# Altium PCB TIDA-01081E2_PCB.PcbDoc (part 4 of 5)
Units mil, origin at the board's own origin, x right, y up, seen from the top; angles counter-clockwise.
Board outline 8611.33 x 3169.64 mil, 4 copper layers (Top Layer, VCC, GND, Bottom Layer), stack 61.6 mil thick; 411 components, 187 nets, 1087 pads, 1987 vias.
Unrouted connection lines stored in the file: 7.
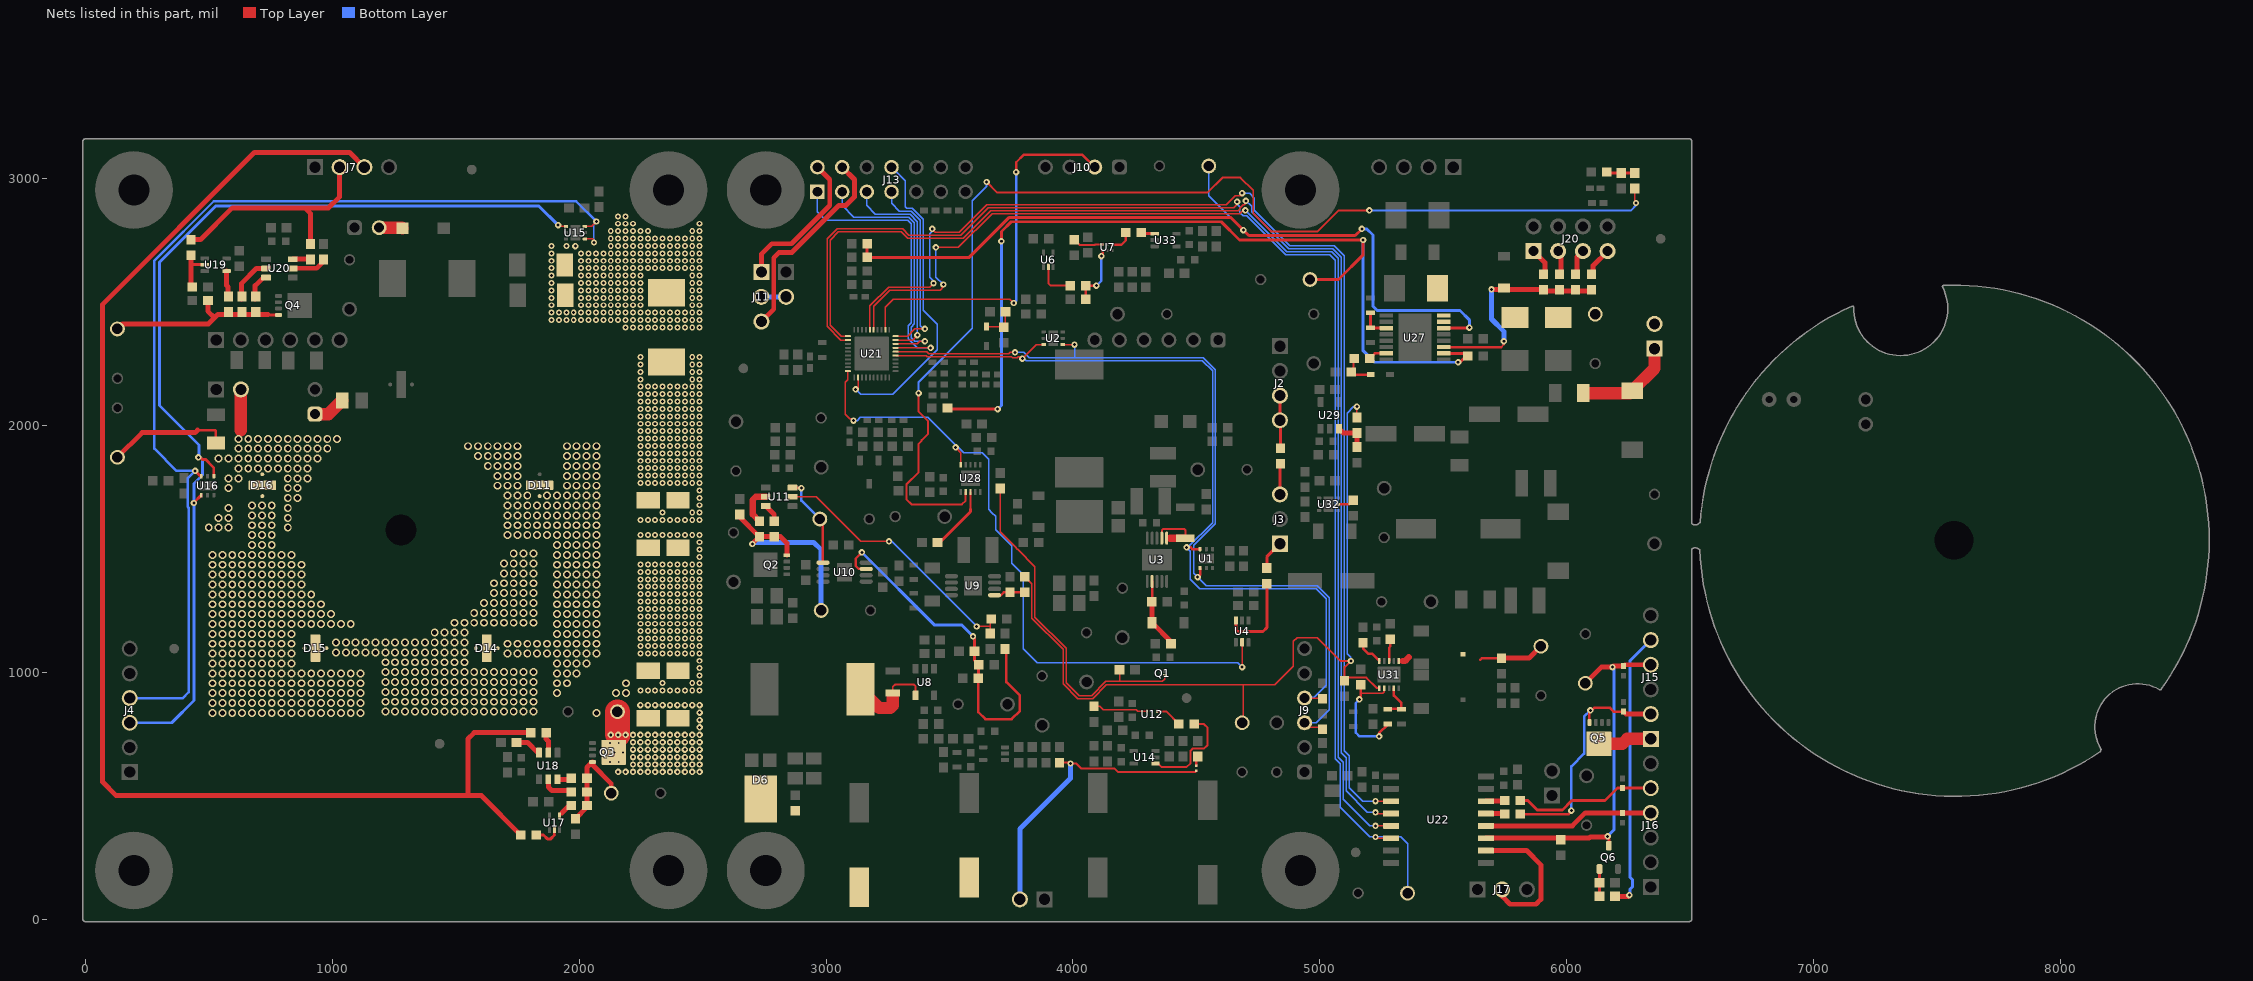
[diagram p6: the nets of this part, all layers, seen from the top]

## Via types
v1: diameter 32, hole 20, Top Layer to Bottom Layer, tented both sides, 779 vias
v2: diameter 26, hole 12, Top Layer to Bottom Layer, tented both sides, 622 vias
v3: diameter 24, hole 12, Top Layer to Bottom Layer, 506 vias
v4: diameter 19.68, hole 7.87, Top Layer to Bottom Layer, 50 vias
v5: diameter 26, hole 12, Top Layer to Bottom Layer, 14 vias
v6: diameter 19.68, hole 7.87, Top Layer to Bottom Layer, tented both sides, 12 vias
v7: diameter 19.68, hole 7.87, Top Layer to Bottom Layer, tented top, 4 vias

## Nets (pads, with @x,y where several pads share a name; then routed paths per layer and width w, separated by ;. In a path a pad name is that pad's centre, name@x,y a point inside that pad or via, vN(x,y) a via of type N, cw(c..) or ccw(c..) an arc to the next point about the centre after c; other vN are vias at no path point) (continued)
NetD10_1: D10.1 R133.2 R134.2
  other v3: 2248,1616 2278,1616 2308,1616 2338,1616 2368,1616 2398,1616 2428,1616 2458,1616 2488,1616 2338,1646 2458,1646 2488,1646 2488,1676 2488,1706 2488,1736 2248,1766 2278,1766 2308,1766 2338,1766 2368,1766 2398,1766 2428,1766 2458,1766 2488,1766 2248,1796 2278,1796 2308,1796 2338,1796 2368,1796 2398,1796 2428,1796 2458,1796 2488,1796 2248,1826 2278,1826 2308,1826 2338,1826 2368,1826 2398,1826 2428,1826 2458,1826 2488,1826 2248,1856 2278,1856 2308,1856 2338,1856 2368,1856 2398,1856 2428,1856 2458,1856 2488,1856 2248,1886 2278,1886 2308,1886 2338,1886 2368,1886 2398,1886 2428,1886 2458,1886 2488,1886 2248,1916 2278,1916 2308,1916 2338,1916 2368,1916 2398,1916 2428,1916 2458,1916 2488,1916 2248,1946 2278,1946 2308,1946 2338,1946 2368,1946 2398,1946 2428,1946 2458,1946 2488,1946 2248,1976 2278,1976 2308,1976 2338,1976 2368,1976 2398,1976 2428,1976 2458,1976 2488,1976 2248,2006 2278,2006 2308,2006 2338,2006 2368,2006 2398,2006 2428,2006 2458,2006 2488,2006 2248,2036 2278,2036 2308,2036 2338,2036 2368,2036 2398,2036 2428,2036 2458,2036 2488,2036 2248,2066 2278,2066 2308,2066 2338,2066 2368,2066 2398,2066 2428,2066 2458,2066 2488,2066 2248,2096 2278,2096 2308,2096 2338,2096 2368,2096 2398,2096 2428,2096 2458,2096 2488,2096 2248,2126 2278,2126 2308,2126 2338,2126 2368,2126 2398,2126 2428,2126 2458,2126 2488,2126 2248,2156 2278,2156 2308,2156 2338,2156 2368,2156 2398,2156 2428,2156 2458,2156 2488,2156 2248,2186 2458,2186 2488,2186 2248,2216 2458,2216 2488,2216 2248,2246 2458,2246 2488,2246 2248,2276 2458,2276 2488,2276
NetD10_2: D10.2 R131.1 R132.1
  other v2: 1985,2725
  other v3: 2188,2396 2218,2396 2248,2396 2278,2396 2308,2396 2338,2396 2368,2396 2398,2396 2428,2396 2458,2396 2488,2396 1888,2426 1918,2426 1948,2426 1978,2426 2008,2426 2038,2426 2068,2426 2098,2426 2128,2426 2158,2426 2188,2426 2218,2426 2248,2426 2278,2426 2308,2426 2338,2426 2368,2426 2398,2426 2428,2426 2458,2426 2488,2426 1888,2456 1918,2456 1948,2456 1978,2456 2008,2456 2038,2456 2068,2456 2098,2456 2128,2456 2158,2456 2188,2456 2218,2456 2248,2456 2278,2456 2308,2456 2338,2456 2368,2456 2398,2456 2428,2456 2458,2456 2488,2456 1888,2486 2008,2486 2038,2486 2068,2486 2098,2486 2128,2486 2158,2486 2188,2486 2218,2486 2248,2486 2458,2486 2488,2486 1888,2516 2008,2516 2038,2516 2068,2516 2098,2516 2128,2516 2158,2516 2188,2516 2218,2516 2248,2516 2458,2516 2488,2516 1888,2546 2008,2546 2038,2546 2068,2546 2098,2546 2128,2546 2158,2546 2188,2546 2218,2546 2248,2546 2458,2546 2488,2546 1888,2576 2008,2576 2038,2576 2068,2576 2098,2576 2128,2576 2158,2576 2188,2576 2218,2576 2248,2576 2458,2576 2488,2576 1888,2606 2008,2606 2038,2606 2068,2606 2098,2606 2128,2606 2158,2606 2188,2606 2218,2606 2248,2606 2458,2606 2488,2606 1888,2636 2008,2636 2038,2636 2068,2636 2098,2636 2128,2636 2158,2636 2188,2636 2218,2636 2248,2636 2278,2636 2308,2636 2338,2636 2368,2636 2398,2636 2428,2636 2458,2636 2488,2636 1888,2666 2008,2666 2038,2666 2068,2666 2098,2666 2128,2666 2158,2666 2188,2666 2218,2666 2248,2666 2278,2666 2308,2666 2338,2666 2368,2666 2398,2666 2428,2666 2458,2666 2488,2666 1888,2696 2008,2696 2038,2696 2068,2696 2098,2696 2128,2696 2158,2696 2188,2696 2218,2696 2248,2696 2278,2696 2308,2696 2338,2696 2368,2696 2398,2696 2428,2696 2458,2696 2488,2696 1888,2726 1948,2726 2128,2726 2158,2726 2188,2726 2218,2726 2248,2726 2278,2726 2308,2726 2338,2726 2368,2726 2398,2726 2428,2726 2458,2726 2488,2726 2128,2756 2158,2756 2188,2756 2218,2756 2248,2756 2278,2756 2308,2756 2338,2756 2368,2756 2398,2756 2428,2756 2458,2756 2488,2756 2128,2786 2158,2786 2188,2786 2218,2786 2248,2786 2278,2786 2458,2786 2488,2786 2158,2816 2188,2816 2218,2816 2488,2816 2158,2846 2188,2846
NetD11_2: D11.2 D11.3 D14.1
  other v1: 2070,835 1910,915 2150,915 2190,915 1910,955 1950,955 2190,955 1910,995 1950,995 1990,995 1910,1035 1950,1035 1990,1035 2030,1035 1710,1075 1750,1075 1790,1075 1830,1075 1870,1075 1910,1075 1950,1075 1990,1075 2030,1075 2070,1075 1710,1115 1750,1115 1790,1115 1830,1115 1870,1115 1910,1115 1950,1115 1990,1115 2030,1115 2070,1115 1910,1155 1950,1155 1990,1155 2030,1155 2070,1155 1910,1195 1950,1195 1990,1195 2030,1195 2070,1195 1910,1235 1950,1235 1990,1235 2030,1235 2070,1235 1910,1275 1950,1275 1990,1275 2030,1275 2070,1275 1910,1315 1950,1315 1990,1315 2030,1315 2070,1315 1910,1355 1950,1355 1990,1355 2030,1355 2070,1355 1910,1395 1950,1395 1990,1395 2030,1395 2070,1395 1910,1435 1950,1435 1990,1435 2030,1435 2070,1435 1910,1475 1950,1475 1990,1475 2030,1475 2070,1475 1910,1515 1950,1515 1990,1515 2030,1515 2070,1515 1710,1555 1750,1555 1790,1555 1830,1555 1870,1555 1910,1555 1950,1555 1990,1555 2030,1555 2070,1555 1710,1595 1750,1595 1790,1595 1830,1595 1870,1595 1910,1595 1950,1595 1990,1595 2030,1595 2070,1595 1710,1635 1750,1635 1790,1635 1830,1635 1870,1635 1910,1635 1950,1635 1990,1635 2030,1635 2070,1635 1710,1675 1750,1675 1790,1675 1830,1675 1870,1675 1910,1675 1950,1675 1990,1675 2030,1675 2070,1675 1710,1715 1750,1715 1790,1715 1870,1715 1910,1715 1950,1715 1990,1715 2030,1715 2070,1715 1670,1755 1710,1755 1750,1755 1950,1755 1990,1755 2030,1755 2070,1755 1670,1795 1710,1795 1750,1795 1950,1795 1990,1795 2030,1795 2070,1795 1630,1835 1670,1835 1710,1835 1750,1835 1950,1835 1990,1835 2030,1835 2070,1835 1590,1875 1630,1875 1670,1875 1710,1875 1750,1875 1950,1875 1990,1875 2030,1875 2070,1875 1550,1915 1590,1915 1630,1915 1670,1915 1710,1915 1750,1915 1950,1915 1990,1915 2030,1915 2070,1915
NetD14_2: D14.2 D14.3 D15.1
  other v1: 1215,840 1255,840 1295,840 1335,840 1375,840 1415,840 1455,840 1495,840 1535,840 1575,840 1615,840 1655,840 1695,840 1735,840 1775,840 1815,840 1215,880 1255,880 1295,880 1335,880 1375,880 1415,880 1455,880 1495,880 1535,880 1575,880 1615,880 1655,880 1695,880 1735,880 1775,880 1815,880 1215,920 1255,920 1295,920 1335,920 1375,920 1415,920 1455,920 1495,920 1535,920 1575,920 1615,920 1655,920 1695,920 1735,920 1775,920 1815,920 1215,960 1255,960 1295,960 1335,960 1375,960 1415,960 1455,960 1495,960 1535,960 1575,960 1615,960 1655,960 1695,960 1735,960 1775,960 1815,960 1215,1000 1255,1000 1295,1000 1335,1000 1375,1000 1415,1000 1455,1000 1495,1000 1535,1000 1575,1000 1615,1000 1655,1000 1695,1000 1735,1000 1775,1000 1815,1000 1215,1040 1255,1040 1295,1040 1335,1040 1375,1040 1415,1040 1455,1040 1495,1040 1535,1040 1015,1080 1055,1080 1095,1080 1135,1080 1175,1080 1215,1080 1255,1080 1295,1080 1335,1080 1375,1080 1415,1080 1455,1080 1495,1080 1535,1080 1015,1120 1055,1120 1095,1120 1135,1120 1175,1120 1215,1120 1255,1120 1295,1120 1335,1120 1375,1120 1415,1120 1455,1120 1495,1120 1535,1120 1415,1160 1455,1160 1495,1160 1535,1160 1495,1200 1535,1200 1575,1200 1615,1200 1655,1200 1695,1200 1735,1200 1775,1200 1815,1200 1575,1240 1615,1240 1655,1240 1695,1240 1735,1240 1775,1240 1815,1240 1615,1280 1655,1280 1695,1280 1735,1280 1775,1280 1815,1280 1655,1320 1695,1320 1735,1320 1775,1320 1815,1320 1655,1360 1695,1360 1735,1360 1775,1360 1815,1360 1695,1400 1735,1400 1775,1400 1815,1400 1695,1440 1735,1440 1775,1440 1815,1440 1735,1480 1775,1480 1815,1480
NetD15_2: D15.2 D15.3 D16.1
  other v1: 515,835 555,835 595,835 635,835 675,835 715,835 755,835 795,835 835,835 875,835 915,835 955,835 995,835 1035,835 1075,835 1115,835 515,875 555,875 595,875 635,875 675,875 715,875 755,875 795,875 835,875 875,875 915,875 955,875 995,875 1035,875 1075,875 1115,875 515,915 555,915 595,915 635,915 675,915 715,915 755,915 795,915 835,915 875,915 915,915 955,915 995,915 1035,915 1075,915 1115,915 515,955 555,955 595,955 635,955 675,955 715,955 755,955 795,955 835,955 875,955 915,955 955,955 995,955 1035,955 1075,955 1115,955 515,995 555,995 595,995 635,995 675,995 715,995 755,995 795,995 835,995 875,995 915,995 955,995 995,995 1035,995 1075,995 1115,995 515,1035 555,1035 595,1035 635,1035 675,1035 715,1035 755,1035 795,1035 835,1035 515,1075 555,1075 595,1075 635,1075 675,1075 715,1075 755,1075 795,1075 835,1075 515,1115 555,1115 595,1115 635,1115 675,1115 715,1115 755,1115 795,1115 835,1115 515,1155 555,1155 595,1155 635,1155 675,1155 715,1155 755,1155 795,1155 835,1155 515,1195 555,1195 595,1195 635,1195 675,1195 715,1195 755,1195 795,1195 835,1195 875,1195 915,1195 955,1195 995,1195 1035,1195 1075,1195 515,1235 555,1235 595,1235 635,1235 675,1235 715,1235 755,1235 795,1235 835,1235 875,1235 915,1235 955,1235 995,1235 515,1275 555,1275 595,1275 635,1275 675,1275 715,1275 755,1275 795,1275 835,1275 875,1275 915,1275 955,1275 515,1315 555,1315 595,1315 635,1315 675,1315 715,1315 755,1315 795,1315 835,1315 875,1315 915,1315 515,1355 555,1355 595,1355 635,1355 675,1355 715,1355 755,1355 795,1355 835,1355 875,1355 515,1395 555,1395 595,1395 635,1395 675,1395 715,1395 755,1395 795,1395 835,1395 875,1395 515,1435 555,1435 595,1435 635,1435 675,1435 715,1435 755,1435 795,1435 835,1435 875,1435 515,1475 555,1475 595,1475 635,1475 675,1475 715,1475 755,1475 795,1475 835,1475 675,1515 715,1515 755,1515 675,1555 715,1555 755,1555 675,1595 715,1595 755,1595 675,1635 715,1635 755,1635 675,1675 715,1675 755,1675
NetD16_2: D16.2 D16.3 J8.2 R67.1 TP13.1 | length 660.7
  Top Layer w10: 455,1980 525,1980 529,1976 R67.1@529,1927.91
  Top Layer w20: TP13.1@130,1870 230,1970 445,1970 455,1980 ; R67.1@529,1927.91 R67.1@530,1928.91
  Top Layer w50: 629,1980 J8.2@629,2145
  other v1: 500,1585 540,1585 580,1585 820,1585 540,1625 580,1625 820,1625 580,1665 820,1665 820,1705 860,1705 580,1745 820,1745 860,1745 580,1785 620,1785 820,1785 860,1785 900,1785 620,1825 660,1825 700,1825 740,1825 780,1825 820,1825 860,1825 900,1825 540,1865 580,1865 620,1865 660,1865 700,1865 740,1865 780,1865 820,1865 860,1865 900,1865 940,1865 620,1905 660,1905 700,1905 740,1905 780,1905 820,1905 860,1905 900,1905 940,1905 980,1905 620,1945 660,1945 700,1945 740,1945 780,1945 820,1945 860,1945 900,1945 940,1945 980,1945 1020,1945
NetD17_2: D17.2 D19.1 D20.1 J22.2 TP15.1 U27.15 U27.16 | length 34.1
  Top Layer w25: D17.2@5477.01,2555 D17.2@5501.14,2530.87
NetD21_1: D21.1 R98.2 R99.2 | length 143.2
  Top Layer w10: R98.2@5138.5,2270 5136,2267.5 5136,2231 5126.5,2221.5 R99.2@5126.5,2215 5136.5,2205 D21.1@5205.63,2205
NetD22_1: D22.1 R101.1 R103.2 R104.2 R106.1 U27.11 | length 906.8
  Top Layer w8: 5568.82,2316.61 5569.13,2316.3 ; 5733.52,2316.3 5744.91,2327.69 v2(5744.91,2340)
  Top Layer w10: U27.11@5501.14,2316.61 5568.82,2316.61 ; 5569.13,2316.3 5733.52,2316.3
  Top Layer w20: v2(5695,2550) 5900,2550 5906.39,2543.61 6102.59,2543.61 R106.1@6106.09,2547.12
  Bottom Layer w20: v2(5695,2550) 5695,2430 5744.91,2380.09 v2(5744.91,2340)
NetD24_1: D24.1 R78.2 R137.1 | length 137.4
  Top Layer w6: D24.1@3650,2399.37 3717.13,2399.37 R78.2@3720,2396.5 3726.5,2402.99 R137.1@3726.5,2460
NetJ2_3: J2.3 J2.4 R7.1 | length 214.3
  Top Layer w12: J2.3@4838,2120 J2.4@4838,2020 4840,2018 R7.1@4840,1906.5
NetJ3_1: J3.1 R8.2 | length 120.5
  Top Layer w12: R8.2@4785,1421.5 4785,1467 J3.1@4838,1520
NetJ3_3: J3.3 R7.2 | length 124.3
  Top Layer w12: J3.3@4838,1720 4838,1841.5 R7.2@4840,1843.5
NetJ5_1: J5.1 L7.2 | length 132.8
  Top Layer w50: J5.1@930,2045 985,2045 L7.2@1040,2100
NetJ7_2: J7.2 R63.1 R69.1 | length 948.4
  Top Layer w20: R63.1@428.11,2751.5 466.61,2751.5 595.11,2880 890,2880 ; R69.1@911.57,2734.31 911.57,2858.43 890,2880 ; J7.2@1030,3045 1030,2925 985,2880 890,2880
NetJ7_3: J7.3 R57.1 R62.1 | length 5554
  Top Layer w20: J7.3@1130,3045 1070,3105 685,3105 70,2490 70,555 125,500 1545,500 ; R57.1@1763.5,340 1605,498.5 1605,500 1545,500 ; R62.1@1803.5,755 1575,755 1550,730 1550,505 1545,500
NetJ11_2: J11.2 J12.2 | length 100
  Bottom Layer w20: J11.2@2738,2520 J12.2@2838,2520
NetJ15_1: J15.1 Q5.5 Q5.6 Q5.7 Q5.8 Q5.9@6130,709.61 | length 247.3
  Top Layer w20: Q5.9@6130,709.61 Q5.9@6150.39,730
  Top Layer w50: Q5.9@6130,709.61 6224.61,709.61 6245,730 J15.1@6340,730
NetJ15_2: J15.2 Q5.4 R86.2 U24.2 | length 954.4
  Top Layer w10: R86.2@5811.5,425 6007.05,425 6021.03,438.97 v2(6018.33,438.97) ; Q5.4@6091.61,796.02 v2@6091.61,836.61 ; v2@6097.5,842.5 6110,855 6175,855 6189.69,840.32 U24.2@6230,840.32
  Top Layer w20: U24.2@6230,840.32 6240.31,830 J15.2@6340,830
  Bottom Layer w10: v2(6018.33,438.97) 6018.33,618.33 6070,670 6070,820 v2(6095,845)
NetJ15_4: J15.4 Q6.3 R87.1 TP25.1 U22.11 U26.2 | length 1516.7
  Top Layer w12: v2@6162.24,332.24 6170,324.49 Q6.3@6170,297.24
  Top Layer w20: U22.11@5671.93,327.41 6090.17,327.41 6095,332.24 v2@6162.24,332.24 ; TP25.1@6075,955 6140,1020 v2(6185,1020) 6189.69,1024.68 U26.2@6230,1024.68 ; U26.2@6235.31,1030 J15.4@6340,1030
  Bottom Layer w12: v2(6165,335) 6190.23,360.23 6190.23,1014.77 v2(6185,1020)
NetJ15_5: J15.5 R47.2 | length 1137.8
  Top Layer w20: R47.2@6194.91,91.96 6248.42,91.96 v2(6253.42,96.96)
  Bottom Layer w12: v2(6253.42,96.96) 6255,98.54 6255,119.64 6265,129.64 6265,160.36 6255,170.36 6255,1045 J15.5@6340,1130
NetJ16_4: J16.4 U22.12 U25.2 | length 689.9
  Top Layer w20: U22.12@5671.93,377.41 6022.26,377.41 6074.85,430 J16.4@6340,430
NetJ16_5: J16.5 R85.2 U23.2 | length 581
  Top Layer w12: R85.2@5811.5,480 5842,480 5880,442 5982,442 6020,480 6155,480 6205.31,530.32 U23.2@6225,530.32 6339.69,530.32 J16.5@6340,530
NetJ17_2: J17.2 U22.10 | length 593.4
  Top Layer w20: U22.10@5671.93,277.41 5837.59,277.41 5895,220 5895,80 5875,60 5770,60 5738,92 J17.2@5738,120
NetJ18_2: J18.2 L6.1 | length 95.2
  Top Layer w50: J18.2@1190,2800 1282.34,2800 L6.1@1284.34,2798
NetJ20_1: J20.1 R101.2 | length 114
  Top Layer w20: J20.1@5865,2705 5911.09,2658.91 R101.2@5911.09,2610.11
NetJ20_3: J20.3 R103.1 | length 99.5
  Top Layer w20: J20.3@5965,2705 5976.09,2693.91 R103.1@5976.09,2610.11
NetJ20_5: J20.5 R104.1 | length 104.8
  Top Layer w20: R104.1@6041.09,2610.11 6041.09,2681.09 J20.5@6065,2705
NetJ20_7: J20.7 R106.2 | length 119.3
  Top Layer w20: R106.2@6106.09,2610.11 6106.09,2646.09 J20.7@6165,2705
NetJ22_1: J22.1 L3.1 R91.2 | length 409.3
  Top Layer w50: R91.2@6067.09,2130 6254.92,2130 L3.1@6265,2140.08 6355,2230.08 J22.1@6355,2310
NetL2_2: L2.2 R20.2 U8.4 | length 356
  Top Layer w8: R20.2@3270,915.71 3270,940 3280,950 3355,950 3362.6,942.4 U8.4@3362.6,905.87
  Top Layer w50: L2.2@3139.88,930 3214.88,855 3260,855 3270,865 3270,895
NetL5_1: L5.1 R115.1 TP18.1 U31.1 | length 314.6
  Top Layer w10: U31.1@5319.37,1045.12 5335.12,1045.12 ; 5650,1050 5656.5,1056.5 R115.1@5735,1056.5
  Top Layer w20: R115.1@5735,1056.5 5846.5,1056.5 TP18.1@5895,1105
  Top Layer w25: 5335.12,1045.12 5345.12,1045.12 5360,1060
NetQ1_1: Q1.1@4371.89,988.11 R6.2 R60.1 | length 1411.2
  Top Layer w6: R60.1@3705,1743.5 3705,1567.59 3769.82,1502.77 3769.82,1502.57 3775.09,1497.3 3775.29,1497.3 3845,1427.59 3845,1228.79 3845.54,1228.24 3845.54,1223.18 3972,1096.72 3972,958 4025,905 4075,905 4132.19,962.19 4185,962.19 ; R6.2@4188.5,1010 4188.5,965.69 4185,962.19 ; Q1.1@4371.89,988.11 4371.89,971.89 4362.19,962.19 4185,962.19
NetQ2_4: Q2.4 R34.2 R35.2 R36.2 TP8.1 | length 874.2
  Top Layer w20: R36.2@2650,1638.5 2650,1628.5 R34.2@2730,1548.5 ; v2(2701.46,1518.98) 2701.46,1519.96 R34.2@2730,1548.5 ; Q2.4@2841.02,1473.39 2841.02,1523.12 2815.64,1548.5 R35.2@2790,1548.5 R34.2@2730,1548.5
  Bottom Layer w20: v2(2701.46,1518.98) 2707.48,1525 2950,1525 2980,1495 TP8.1@2980,1250
NetQ3_4: Q3.4 R58.2 R59.2 R61.2 R129.2 TP12.1 | length 416.6
  Top Layer w10: 2053.98,624.24 2053.98,636.46 Q3.4@2053.98,636.61
  Top Layer w20: R59.2@1985,406.5 2031.5,452.99 R58.2@2031.5,460 R129.2@2031.5,515 R61.2@2031.5,570 2031.5,613.98 Q3.4@2053.98,636.46 ; 2053.98,624.24 2130,548.21 TP12.1@2130,510
NetQ3_5: Q3.5 Q3.6 Q3.7 Q3.8 Q3.9@2140.39,675 R135.1 R136.1 TP26.1 | length 95.2
  Top Layer w100: TP26.1@2155,840 2155,749 v2(2158,746)
  other v2: 2158,596 2188,596 2218,596 2248,596 2278,596 2308,596 2338,596 2368,596 2398,596 2428,596 2458,596 2488,596 2218,626 2248,626 2278,626 2308,626 2338,626 2368,626 2398,626 2428,626 2458,626 2488,626 2218,656 2248,656 2278,656 2308,656 2338,656 2368,656 2398,656 2428,656 2458,656 2488,656 2218,686 2248,686 2278,686 2308,686 2338,686 2368,686 2398,686 2428,686 2458,686 2488,686 2218,716 2248,716 2278,716 2308,716 2338,716 2368,716 2398,716 2428,716 2458,716 2488,716 2128,746 2188,746 2218,746 2248,746 2278,746 2308,746 2338,746 2368,746 2398,746 2428,746 2458,746 2488,746 2488,776 2488,806 2488,836 2248,866 2278,866 2308,866 2338,866 2368,866 2398,866 2428,866 2458,866 2488,866
  other v4: 2124.65,636.61 2160.28,636.61 2106.83,675 2142.46,675 2178.09,675 2124.65,713.39 2160.28,713.39
NetQ4_4: Q4.4 R64.2 R66.2 R68.2 R70.2 TP14.1 | length 758.1
  Top Layer w12: 739.6,2448.5 741.49,2446.61 Q4.4@782.08,2446.61
  Top Layer w20: TP14.1@130,2390 150,2410 498.11,2410 523.11,2435 ; R66.2@496.5,2505 496.5,2461.61 523.11,2435 ; 739.6,2448.5 536.61,2448.5 523.11,2435
NetQ6_1: Q6.1 R47.1 R84.2 | length 111.1
  Top Layer w12: R47.1@6131.92,91.96 6132.6,92.64 Q6.1@6132.6,202.76
NetR3_1: R3.1 U3.6 U3.7 | length 240
  Top Layer w8: U3.7@4359.69,1542.6 4360,1542.91 4360,1574.02 4365.98,1580 4450,1580 4455,1575 R3.1@4455,1542.01
  Top Layer w12: U3.6@4379.37,1542.6 4392.6,1542.6
  Top Layer w20: 4392.6,1542.6 4393.19,1542.01
  Top Layer w30: 4393.19,1542.01 R3.1@4455,1542.01
NetR8_1: R8.1 U4.6 | length 351.1
  Top Layer w12: U4.6@4659.41,1209.29 4659.41,1170.91 4665.31,1165 4770,1165 4785,1180 R8.1@4785,1358.5
NetR14_2: R14.2 R18.2 U7.4 | length 252.2
  Top Layer w10: R14.2@4051.5,2510 R18.2@4051.5,2565 v2(4095,2565) ; v2(4115,2685) 4120.31,2690.31 U7.4@4120.31,2708.19
  Bottom Layer w10: v2(4095,2565) 4115,2585 v2(4115,2685)
NetR17_1: R17.1 U7.1 | length 92.6
  Top Layer w10: U7.1@4159.69,2730.83 4195.83,2730.83 4213.5,2748.5 R17.1@4213.5,2780
NetR17_2: R17.2 U33.1 | length 56
  Top Layer w12: R17.2@4276.5,2780 4280.91,2775.59 U33.1@4330.71,2775.59
NetR18_1: R18.1 U6.2 | length 158.5
  Top Layer w8: U6.2@3900,2640.87 3900,2575 3910,2565 R18.1@3988.5,2565
NetR19_2: R19.2 U7.3 | length 125
  Top Layer w8: R19.2@4005,2751.5 4026.5,2730 4088.54,2730 4090.35,2731.81 U7.3@4120.31,2731.81
NetR22_2: R22.2 R24.2 U9.5 | length 127.3
  Top Layer w10: U9.5@3682.6,1311.61 3708.41,1311.61 3720.3,1323.5 R24.2@3745,1323.5 R22.2@3805,1323.5
NetR34_1: R34.1 U11.2 | length 155.7
  Top Layer w25: R34.1@2730,1611.5 2702.8,1638.7 2702.8,1697.8 2715,1710 U11.2@2755.87,1710
NetR35_1: R35.1 U11.3 | length 75.2
  Top Layer w20: U11.3@2755.87,1672.6 2790,1638.46 R35.1@2790,1611.5
NetR37_1: R37.1 R41.1 R45.2 R50.2 U10.7 | length 1488.4
  Top Layer w10: v2(3145,1485) 3120,1460 3120,1430 3132.2,1417.8 U10.7@3162.6,1417.8 ; R41.1@3616.5,975 3616.5,838.5 3645,810 3751.69,810 3785,843.31 3785,905 3730,960 3730,1088.5 R37.1@3725,1093.5
  Top Layer w12: v2(3595,1145) 3601.5,1138.5 R50.2@3601.5,1085 3601.5,1047.01 3616.5,1032.01 R41.1@3616.5,975
  Bottom Layer w12: v2(3145,1485) 3440,1190 3550,1190 v2(3595,1145)
NetR38_1: R38.1 R44.1 U11.5 | length 1079.4
  Top Layer w6: U11.5@2864.13,1710 2960,1710 3140,1530 v2(3255,1530) ; v2(3610,1185) 3662.2,1185 3665,1187.8 ; R38.1@3665,1156.5 3665,1187.8 ; R44.1@3668.5,1215 3665,1211.5 3665,1187.8
  Bottom Layer w6: v2(3255,1530) 3265,1530 v2(3610,1185)
NetR46_1: R46.1 U12.1 | length 109.9
  Top Layer w8: U12.1@4339.69,840.83 4377.68,840.83 R46.1@4428.5,790
NetR46_2: R46.2 U14.1 | length 413.3
  Top Layer w8: U14.1@4334.29,629.41 4345.59,629.41 4360,615 4459.57,615 4476.3,631.73 4476.3,682.33 4483.97,690 4530,690 4545,705 4545,775 4530,790 R46.2@4491.5,790
NetR51_2: R51.2 U12.3 | length 223.5
  Top Layer w6: R51.2@4085,861.5 4107.39,861.5 4121.7,847.19 4256.49,847.19 4261.87,841.81 U12.3@4300.31,841.81
NetR57_2: R57.2 U17.2 | length 106.8
  Top Layer w10: 1900,340 U17.2@1900,360.87
  Top Layer w12: R57.2@1826.5,340 1856,340 1871,325 1885,325 1900,340
NetR58_1: R58.1 U17.4 | length 65.7
  Top Layer w10: U17.4@1919.68,419.13 1930,429.45
  Top Layer w20: 1930,429.45 1960.55,460 R58.1@1968.5,460
NetR61_1: R61.1 U18.3 | length 57.8
  Top Layer w20: U18.3@1912.4,565.87 1964.37,565.87 R61.1@1968.5,570
NetR62_2: R62.2 U18.5 | length 84.8
  Top Layer w20: R62.2@1866.5,755 1866.5,728.5 1870,725 ; 1870.75,725.75 1875,721.5 U18.5@1875,674.13
NetR63_2: R63.2 R65.2 U19.2 | length 187.2
  Top Layer w12: 428.11,2648.11 430,2650 U19.2@483.82,2650
  Top Layer w20: R63.2@428.11,2688.5 428.11,2565.4 R65.2@433.5,2560
NetR64_1: R64.1 U19.4 | length 107.2
  Top Layer w20: U19.4@572.4,2624.41 572.4,2565.71 578.11,2560 578.11,2521.5 R64.1@580,2521.5
NetR68_1: R68.1 U20.2 | length 187.5
  Top Layer w20: R68.1@633.11,2511.5 633.11,2575 693.11,2635 U20.2@732.22,2635
NetR69_2: R69.2 U20.6 | length 68.1
  Top Layer w20: U20.6@840.49,2672.4 907,2672.4 R69.2@908.11,2673.5
NetR70_1: R70.1 U20.3 | length 111.1
  Top Layer w20: R70.1@688.11,2511.5 688.11,2565 720.7,2597.6 U20.3@732.22,2597.6
NetR85_1: R85.1 U22.14 | length 77.6
  Top Layer w20: U22.14@5671.93,477.41 5745.92,477.41 R85.1@5748.5,480
NetR86_1: R86.1 U22.13 | length 77.6
  Top Layer w20: U22.13@5671.93,427.41 5746.09,427.41 R86.1@5748.5,425
NetR89_2: R89.2 U18.6 | length 108
  Top Layer w20: R89.2@1746.5,715 1791.81,715 1832.68,674.13 U18.6@1837.6,674.13
NetR90_2: R90.2 U20.5 | length 136.4
  Top Layer w20: U20.5@840.49,2635 841.12,2635.63 936.9,2635.63 R90.2@965,2663.73
NetR94_1: R94.1 R95.2 U27.3 | length 122.2
  Top Layer w12: R94.1@5205,2453.5 5205,2396.5 5208.11,2393.39 U27.3@5268.86,2393.39
NetR96_1: R96.1 R97.1 TP28.1 U27.14 | length 3376.8
  Top Layer w12: R96.1@3166.5,2735 R97.1@3166.5,2680 3580,2680 3742,2842 4638,2842 4712,2768 5143,2768 v2(5170,2795) ; U27.14@5501.14,2393.39 5601.89,2393.39 v2@5603.5,2395
  Bottom Layer w6: TP28.1@4550,3050 4550,2930 v5(4690,2790)
  Bottom Layer w12: v2(5170,2795) 5190,2795 5215,2770 5215,2481.69 5231.69,2465 5567.01,2465 5605,2427.01 v2(5605,2395)
NetR98_1: R98.1 U27.7 | length 76.1
  Top Layer w10: R98.1@5201.5,2270 5222.52,2291.02 U27.7@5268.86,2291.02
NetR100_1: R100.1 R102.2 TP29.1 U27.10 | length 3761.4
  Top Layer w12: R100.1@3491.5,2065 v2(3695,2065) ; v2(3710,2745) 3710,2784.54 3749.46,2824 4600.54,2824 4674.54,2750 v2(5175,2750) 5175,2690 5075,2590 TP29.1@4960,2590 ; U27.10@5501.14,2291.02 5592.48,2291.02 5598.5,2285 5597.28,2285 5567.28,2255 v2(5560,2255)
  Bottom Layer w12: v2(3695,2065) 3710,2080 v2(3710,2745) ; v2(5175,2750) 5175,2301.22 5221.22,2255 v2(5560,2255)
NetR105_1: R105.1 U28.3 | length 265.2
  Top Layer w8: 3585,1661.5 U28.3@3585,1729.88
  Top Layer w12: R105.1@3451.5,1525 3460,1525 3585,1650 3585,1661.5
NetR108_2: R108.2 R127.2 R128.1 | length 115
  Top Layer w12: R108.2@6161.5,3025 6165,3021.5 R128.1@6220,3021.5 R127.2@6275,3021.5
NetR111_2: R111.2 R114.2 U29.3 | length 136.8
  Top Layer w20: U29.3@5077.4,1985.87 5094.76,1968.5 R111.2@5150,1968.5 R114.2@5150,1911.5
NetR116_1: R116.1 R117.2 U31.7 | length 480.2
  Top Layer w6: 5165,910 5169.07,914.07 5254.07,914.07 5260.31,920.31 U31.7@5260.31,934.88
  Top Layer w10: v2(5160,890) 5160,895 5165,900 5165,910 R116.1@5165,948.5 ; v2(5240,740) 5240,753.5 R117.2@5275,788.5
  Bottom Layer w10: v2(5160,890) 5145,875 5145,755 5160,740 v2(5240,740)
NetR117_1: R117.1 R120.2 U31.9 | length 150.9
  Top Layer w10: R117.1@5275,851.5 5330,851.5 5330,875 5299.69,905.32 U31.9@5299.69,934.88
NetR119_1: R119.1 U32.2 | length 68.4
  Top Layer w10: U32.2@5073.39,1680 5118.5,1680 R119.1@5135,1696.5
NetR122_2: R122.2 U31.5 | length 109.8
  Top Layer w10: R122.2@5175,1118.5 5175,1095 5195,1075 5210.75,1075 U31.5@5240.63,1045.12
NetR123_2: R123.2 U31.3 | length 90.5
  Top Layer w10: U31.3@5280,1045.12 5280,1098.98 5285,1103.98 R123.2@5285,1133.5
NetR127_1: R127.1 U28.2 | length 4673.8
  Top Layer w8: v2(3375,2130) 3375,2055 3413,2017 3413,1965.47 3387.18,1939.65 3387.18,1936.39 3375,1924.21 3375,1810 3325,1760 3325,1700 3345.98,1679.02 3550,1679.02 3565.31,1694.34 U28.2@3565.31,1729.88 ; v2(3650,2985) 3693,2942 4544.47,2942 4605.47,3003 4678,3003 4730,2951 4730,2857.72 4802.44,2785.28 4990.63,2785.28 5075.36,2870 v2(5200,2870) ; R127.1@6275,2958.5 6275,2905 v2(6280,2900)
  Bottom Layer w8: v2(3375,2130) 3375,2175 3592,2392 3592,2909.53 3650,2967.53 v2(3650,2985) ; v2(5200,2870) 6260,2870 6280,2890 v2(6280,2900)
NetR129_1: R129.1 U18.2 | length 132.7
  Top Layer w20: U18.2@1875,565.87 1875,535 1890,520 1963.5,520 R129.1@1968.5,515
NetR133_1: R133.1 R134.1 R135.2 R136.2
  other v3: 2248,926 2278,926 2308,926 2338,926 2368,926 2398,926 2428,926 2458,926 2488,926 2338,956 2458,956 2488,956 2488,986 2488,1016 2488,1046 2248,1076 2278,1076 2308,1076 2338,1076 2368,1076 2398,1076 2428,1076 2458,1076 2488,1076 2248,1106 2278,1106 2308,1106 2338,1106 2368,1106 2398,1106 2428,1106 2458,1106 2488,1106 2248,1136 2278,1136 2308,1136 2338,1136 2368,1136 2398,1136 2428,1136 2458,1136 2488,1136 2248,1166 2278,1166 2308,1166 2338,1166 2368,1166 2398,1166 2428,1166 2458,1166 2488,1166 2248,1196 2278,1196 2308,1196 2338,1196 2368,1196 2398,1196 2428,1196 2458,1196 2488,1196 2248,1226 2278,1226 2308,1226 2338,1226 2368,1226 2398,1226 2428,1226 2458,1226 2488,1226 2248,1256 2278,1256 2308,1256 2338,1256 2368,1256 2398,1256 2428,1256 2458,1256 2488,1256 2248,1286 2278,1286 2308,1286 2338,1286 2368,1286 2398,1286 2428,1286 2458,1286 2488,1286 2248,1316 2278,1316 2308,1316 2338,1316 2368,1316 2398,1316 2428,1316 2458,1316 2488,1316 2248,1346 2278,1346 2308,1346 2338,1346 2368,1346 2398,1346 2428,1346 2458,1346 2488,1346 2248,1376 2278,1376 2308,1376 2338,1376 2368,1376 2398,1376 2428,1376 2458,1376 2488,1376 2248,1406 2278,1406 2308,1406 2338,1406 2368,1406 2398,1406 2428,1406 2458,1406 2488,1406 2248,1436 2278,1436 2308,1436 2338,1436 2368,1436 2398,1436 2428,1436 2458,1436 2488,1436 2488,1466 2488,1496 2488,1526 2248,1556 2278,1556 2308,1556 2338,1556 2368,1556 2398,1556 2428,1556 2458,1556 2488,1556
NetTP9_1: TP9.1 U10.1 U11.6 | length 379.7
  Top Layer w10: U11.6@2864.13,1747.4 2897.6,1747.4 v2(2900,1745) v2@2905,1745 ; TP9.1@2975,1620 2987.4,1607.6 U10.1@2987.4,1443.39
  Bottom Layer w10: v2(2900,1745) 2900,1695 TP9.1@2975,1620
PG_5V-BUCK: R22.1 R111.1 R112.1 TP19.1 U31.6 | length 3403.6
  Top Layer w6: R22.1@3805,1386.5 3833,1358.5 3833,1223.82 3833.54,1223.27 3833.54,1218.21 3960,1091.75 3960,953.03 4020.03,893 4079.97,893 4135.16,948.19 4690,948.19 ; TP19.1@4685,795 4690,800 4690,948.19 ; 5085,1045 4989.98,1140.02 4908.41,1140.02 4893,1124.62 4893,1024.62 4816.57,948.19 4690,948.19 ; R111.1@5150,2031.5 v2(5150,2075)
  Top Layer w8: 5085,1045 v2(5125,1045) 5100,1020 R112.1@5100,965.32 5112.87,978.19 5187.84,978.19 5231.15,934.88 U31.6@5240.63,934.88
  Bottom Layer w6: v2(5125,1045) 5125,1060 5110,1075 5110,2049.13 5135.87,2075 v2(5150,2075) v2@5150,2073
SCL: J4.3 J9.3 R72.1 U1.1 U2.1 U15.1 U16.1 U16.4 U21.6 | length 7694.3
  Top Layer w6: v2(1915,2810) 1919.41,2805.59 U15.1@1946.61,2805.59 ; U21.6@3281.46,2297.87 3407.13,2297.87 3415,2290 3740,2290 3745,2295 v2(3765,2295) ; U2.1@3958.39,2326.41 v5@4006.07,2326.41 ; v5(4006.19,2326.53) 4009.66,2330 v5@4010,2330 ; J9.3@4938,795 4956.62,776.38 5010,776.38 R72.1@5003.62,770
  Top Layer w10: 514.87,1833.23 520.59,1827.52 U16.4@520.59,1793.39 ; v2(4505,1385) 4514.41,1394.41 U1.1@4514.41,1421.61
  Top Layer w12: v2(440,1685) 440,1687.2 U16.1@469.41,1716.61 ; v2@460,1870 v2(457.5,1870) 465,1870 473.25,1861.75 486.36,1861.75 514.87,1833.23
  Bottom Layer w6: v2(3765,2295) 3801.11,2295 3822.14,2273.97 3990,2273.97 4010,2273.97 ; v5(4006.19,2326.53) 4006.19,2277.78 4010,2273.97 ; J9.3@4938,795 4985,795 5038,848 5038,1302 4990,1350 4540,1350 v2(4505,1385) 4490,1400 4490,1513.03 4577,1600.03 4577,2224.97 4528,2273.97 4010,2273.97
  Bottom Layer w12: J4.3@180,795 350.13,795 440,884.87 v2(440,1685) 440,1763.55 475,1798.55 475,1860 465,1870 v2(457.5,1870) 460,1872.5 460,1920 300,2080 300,2660.43 527.82,2888.25 1836.75,2888.25 v2(1915,2810)
SCLK: U4.2 U21.30 U28.10 | length 2781.9
  Top Layer w6: U21.30@3088.54,2219.13 3088.54,2184.92 3078,2174.38 3078,2044.87 3096.87,2026 3103.36,2026 v2(3111.03,2018.33) ; v2(3525,1910) 3545.63,1889.37 U28.10@3545.63,1840.12 ; v2(4685,1020) U4.2@4685,1120.71
  Bottom Layer w6: v2@3105,2025 v2@3111.67,2018.33 ; v2(3111.03,2018.33) v2@3111.67,2018.33 ; v2(4685,1020) 4667,1038 3855.03,1038 3798,1095.03 3798,1395.03 3751.84,1441.19 3751.84,1512.16 3686.51,1577.49 3686.51,1630.51 3671.03,1646 3670.92,1646 3658,1658.92 3658,1862.41 3632.41,1888 3558.3,1888 3536.3,1910 v2(3525,1910) 3525,1918.03 3504.75,1938.28 3411.51,2031.51 3138.43,2031.51 3125.26,2018.33 v2@3111.67,2018.33
SDA: J4.4 J9.4 R71.1 U1.6 U2.6 U15.4 U15.6 U16.6 U21.5 | length 7797.7
  Top Layer w6: U15.4@2023.39,2754.41 2055.59,2754.41 2060,2750 v2(2060,2740) ; U15.6@2023.39,2805.59 2050.59,2805.59 v2(2070,2825) ; U21.5@3281.46,2282.13 3405.9,2282.13 3410.03,2278 3750.89,2278 3755.89,2273 3774.11,2273 3779.11,2278 3793.97,2278 3795,2276.97 v2(3795,2270) 3851.41,2326.41 U2.6@3881.61,2326.41 ; J9.4@4956.62,876.38 J9.4@4938,895 5007.13,895 R71.1@5010,892.13
  Top Layer w10: v2(4460,1505) 4476.77,1505 4483.39,1498.39 U1.6@4514.41,1498.39
  Top Layer w12: v2(445,1815) 466.61,1793.39 U16.6@469.41,1793.39
  Bottom Layer w6: v2(2060,2740) 2060,2815 v2(2070,2825) ; v2(3795,2270) 3801.97,2270 3810,2261.97 4523.03,2261.97 4565,2220 4565,1605 4465,1505 v2(4460,1505) 4475,1490 4475,1375.79 4512.79,1338 4985.03,1338 5026,1297.03 5026,946 4978,898 4941,898 J9.4@4938,895
  Bottom Layer w10: J4.4@180,895 395,895 418.68,918.68 418.68,1665.17 414.13,1669.73 414.13,1784.13 v2(445,1815) 370,1815 280,1905 280,2667.13 520,2907.13 1987.87,2907.13 v2(2070,2825)
SHORT_LED: J10.2 U21.12 | length 1557.1
  Top Layer w6: U21.12@3240.12,2386.46 3240.12,2478.15 3272.97,2511 3744,2511 v2(3760,2495)
  Top Layer w10: v2(3770,3025) 3770,3065 3800,3095 4038,3095 J10.2@4088,3045
  Bottom Layer w10: v2(3760,2495) 3770,2505 v2(3770,3025)
TCK: J13.7 U21.10 | length 772.6
  Top Layer w6: U21.10@3281.46,2360.87 3330.87,2360.87 3360,2390 v2(3400,2390)
  Bottom Layer w6: J13.7@3265,2945 3265,2899 3297,2867 3344.97,2867 3382,2829.97 3382,2403 3395,2390 v2(3400,2390)
TDI: J13.3 U21.8 | length 1031.6
  Top Layer w6: U21.8@3281.46,2329.37 3369.37,2329.37 3380,2340 v2(3400,2340)
  Bottom Layer w6: J13.3@3065,2945 3065,2890 3112,2843 3335.03,2843 3358,2820.03 3358,2410 3345,2397 3345,2355 3360,2340 v2(3400,2340)
TDO: J13.1 U21.7 | length 1201.1
  Top Layer w6: U21.7@3281.46,2313.62 v2(3423.62,2313.62) v2@3425,2315
  Bottom Layer w6: J13.1@2965,2945 2965,2865 2999,2831 3330.06,2831 3345,2816.06 3345,2415 3333,2403 3333,2350.03 3369.41,2313.62 v2(3423.62,2313.62)
TEST: J13.8 U21.32 | length 1316.9
  Top Layer w6: v2(3120,2145) 3129.76,2145 3129.88,2145.12 U21.32@3129.88,2193.54 ; J13.8@3265,3030 J13.8@3265,3045
  Bottom Layer w6: v2(3120,2145) 3140,2125 3270,2125 3450,2305 3450,2409 3394,2465 3394,2834.94 3349.94,2879 3326,2879 3320,2885 3320,2990 J13.8@3265,3045
TMS: J13.5 U21.9 | length 843.7
  Top Layer w6: U21.9@3281.46,2345.12 3350.12,2345.12 v2(3370,2365)
  Bottom Layer w6: J13.5@3165,2945 3165,2890 3200,2855 3340,2855 3370,2825 v2(3370,2365)
TRIGGER_IN: TP24.1 U21.22 U22.6 | length 5549.9
  Top Layer w6: U21.22@3088.54,2345.12 3088.43,2345 3060,2345 3005,2400 3005,2755 3045,2795 3310,2795 3335,2770 3545,2770 3656,2881 4651,2881 4665,2895 v2(4665,2905) ; v2(5225,332.41) 5230,327.41 U22.6@5288.07,327.41
  Bottom Layer w6: v2(4665,2905) 4665,2895 4678.49,2881.51 4676.08,2879.11 4676.08,2860.89 4688.97,2848 4703.11,2848 4861.11,2690 5040,2690 5062,2668 5062,650 5082,630 5082,451.96 5201.55,332.41 v2(5225,332.41) 5327.58,332.41 5355,304.99 TP24.1@5355,105
TRIGGER_OUT: U21.21 U22.4 | length 5106.5
  Top Layer w6: U21.21@3088.54,2360.87 3061.1,2360.87 3017,2404.97 3017,2750.03 3049.97,2783 3305.03,2783 3330.03,2758 3556.03,2758 3667.03,2869 4670.11,2869 4676.08,2874.97 4676.08,2879.11 4688.97,2892 4693.11,2892 4705,2903.89 v2(4700,2908.89) ; v2(5225,432.41) 5230,427.41 U22.4@5288.07,427.41
  Bottom Layer w6: v2@4706.11,2910 4705,2908.89 v2(4700,2908.89) 4723,2885.89 4723,2864.72 4873.72,2714 5052.97,2714 5086,2680.97 5086,674 5106,654 5106,519 5192.59,432.41 v2(5225,432.41)
UCA0RXD: U21.15 U22.5 | length 4796.1
  Top Layer w6: U21.15@3192.87,2386.46 3192.87,2481.82 3258.06,2547 3462,2547 3475,2560 v2(3475,2570) v2@3475,2569.75 ; v2(3445,2720) 3535,2720 3672,2857 4675.08,2857 4693.08,2875 v2(4698.08,2870) ; v2(5225,377.41) U22.5@5288.07,377.41
  Bottom Layer w6: v2(3445,2720) 3445,2600 v2(3475,2570) ; v2(4698.08,2870) 4866.08,2702 5048,2702 5074,2676 5074,654.97 5094,634.97 5094,484.96 5201.55,377.41 v2(5225,377.41)
UCA0TXD: U21.16 U22.3 | length 4868.4
  Top Layer w6: U21.16@3177.13,2386.46 3177.13,2483.04 3253.09,2559 3419,2559 v2(3435,2575) ; v2(3430,2795) 3443,2782 3540.03,2782 3651.03,2893 4621,2893 4658,2930 4680,2930 4685,2935 v2(4685,2940) ; v2(5225,477.41) U22.3@5288.07,477.41
  Bottom Layer w6: v2(3430,2795) 3440,2795 3420,2775 3420,2600 3435,2585 v2(3435,2575) ; v2(4685,2940) 4715,2940 4735,2920 4735,2869.69 4878.69,2726 5057.94,2726 5098,2685.94 5098,682 5118,662 5118,532 5172.59,477.41 v2(5225,477.41)
VCC: C3.1 D2.2 R10.2 U3.2 | length 284
  Top Layer w10: C3.1@4320.31,1286.81 U3.2@4320.31,1367.4
  Top Layer w20: C3.1@4320.31,1286.81 4320.31,1200.22 D2.2@4320.53,1200 4396.5,1124.04 R10.2@4396.5,1115
VCC_TARGET: J11.3 J13.4 | length 848.7
  Top Layer w20: J11.3@2738,2420 2788,2470 2788,2678 2810,2700 2861.77,2700 3051.77,2890 3080,2890 3115,2925 3115,2995 J13.4@3065,3045
VCC_TOOL: J11.1 J13.2 | length 607.3
  Top Layer w20: J11.1@2738,2620 2738,2693 2780,2735 2860,2735 3015,2890 3015,2995 J13.2@2965,3045
VOUT_BOOST_1: C18.2 C26.1 C27.1 D6.3 J21.2 NT1.1 R48.1 | length 1207.7
  Top Layer w8: R48.1@3945.31,633.5 3986.5,633.5 v2(3990,630) 4013.45,630 4034.47,608.98 4062,608.98 4062.16,608.82 4168.7,608.82 4182.52,595 4495,595 NT1.1@4500,600
  Bottom Layer w20: J21.2@3784.71,80 3784.71,364.71 3990,570 v2(3990,630)
VOUT_BOOST_2: NT1.2 R49.1 | length 40.6
  Top Layer w10: NT1.2@4500,620 4500,653.5 R49.1@4505,658.5
pads on no net: D9. D11. D14. D15. D16. FID1.1 FID2.1 FID3.1 FID4.1 FID5.1 FID6.1 H1.1 H2.1 H3.1 H4.1 H5.0 H6.0 H7.0 H9.1 H10.1 H11.1 H12.1 J4.5 J9.5 J13.6 J13.10 J13.12 J13.13 J13.14 J16.2 J16.3 J16.6 Q1.1@4371.89,987.13 Q1.2@4371.89,1002.87 Q2.9@2733.74,1396.61 Q2.9@2733.74,1422.2 Q2.9@2733.74,1447.8 Q2.9@2733.74,1473.39 Q2.9@2752.54,1408.92 Q2.9@2752.54,1461.08 Q2.9@2767.11,1435 Q2.9@2788.17,1408.92 Q2.9@2788.17,1461.08 Q3.9@2106.83,648.92 Q3.9@2106.83,701.08 Q3.9@2127.89,675 Q3.9@2142.46,648.92 Q3.9@2142.46,701.08 Q3.9@2161.26,636.61 Q3.9@2161.26,662.2 Q3.9@2161.26,687.8 Q3.9@2161.26,713.39 Q4.9@834.94,2458.92 Q4.9@834.94,2511.08 Q4.9@856,2485 Q4.9@870.57,2458.92 Q4.9@870.57,2511.08 Q4.9@889.37,2446.61 Q4.9@889.37,2472.2 Q4.9@889.37,2497.8 Q4.9@889.37,2523.39 Q5.9@6091.61,688.74 Q5.9@6103.92,707.54 Q5.9@6103.92,743.17 Q5.9@6117.2,688.74 Q5.9@6130,722.11 Q5.9@6142.8,688.74 Q5.9@6156.08,707.54 Q5.9@6156.08,743.17 Q5.9@6168.39,688.74 SH-J3.0 SH-J5.0 SH-J8.0 SH-J11.0 SH-J12.0 SH-J17.0 SH-J18.0 SH-J20.0 SH-J21.0 SH-J22.0 U1.7@4522.28,1460 U1.7@4557.72,1460 U2.7@3920,2334.28 U2.7@3920,2369.72 U3.0 U15.7@1985,2762.28 U15.7@1985,2797.72 U16.7@477.28,1755 U16.7@512.72,1755 U17.1 U19.1 U21.24 U22.7 U27.4 U27.13 U27.17@5385,2355 U28.4 U28.5 U29.4 U31.11@5219.76,980.16 U31.11@5219.76,999.84 U31.11@5255.2,990 U31.11@5304.8,990 U31.11@5340.24,980.16 U31.11@5340.24,999.84 U32.7@5035,1662.28 U32.7@5035,1697.72
copper on no net: | length 1047.4
  VCC w0: 1883.07,2753.18 1883.07,2848.07 1900,2865 1935,2865 2070.02,2865 2100,2835.02 2100,2750 2085,2735
  GND w0: 1883.07,2753.18 1883.07,2848.07 1900,2865 2090,2865 2100,2855 2100,2755 2092.21,2747.21 2092.21,2727.79
  Bottom Layer w0: 1915,2745 1915,2786.55 ; 1915,2845 2030,2845

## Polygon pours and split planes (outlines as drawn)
GND on Top Layer "TOP_LAYER_GND_P492" (solid, remove dead copper, pour order 492): 5000,360 5060,360 5080,380 5080,450 5201.38,450 5190,480 5201.38,491.38 5201.38,550 5191.38,560 5148.54,560 5078.54,490 5000,490 4980,470 4980,380
BOOST_VOUT/BUCK_VIN on Top Layer "TOP_LAYER_BOOST_VOUT/BUCK_VIN_P446" (solid, remove dead copper, pour order 446): 4575,855 4888,855 4888,340 4815,340 4575,340
BOOST_VOUT/BUCK_VIN on Top Layer "TOP_LAYER_BOOST_VOUT/BUCK_VIN_P444" (solid, remove dead copper, pour order 444): 3840,300 4675,300 4675,40 4674.1,39.1 3840,39.1
5V-BUCK_OUT on Top Layer "TOP_LAYER_5V-BUCK_OUT_P442" (solid, remove dead copper, pour order 442): 4870,1400 5010,1400 5010,1215 4870,1215
GND on Top Layer "TOP_LAYER_GND_P440" (solid, remove dead copper, pour order 440): 4982.15,2085.29 5097.72,2085.29 5097.72,2002.68 4982.15,2002.68
GND on Top Layer "TOP_LAYER_GND_P438" (solid, remove dead copper, pour order 438): 5130,1240 5355,1240 5355,1185 5350,1180 5335,1165 5130,1165
FILTER_OUT on Top Layer "TOP_LAYER_FILTER_OUT_P436" (solid, remove dead copper, pour order 436): 5310,1180 5310,1065 5370.2,1065 5370.63,1064.57 5380,1073.94 5385,1180
FILTER_OUT on Top Layer "TOP_LAYER_FILTER_OUT_P434" (solid, remove dead copper, pour order 434): 5670,1385 5800,1385 5800,1175 5670,1175
NetC73_1 on Top Layer "TOP_LAYER_NETC73_1_P430" (solid, remove dead copper, pour order 430): 5320,2431.57 5425,2431.57 5425,2643.58 5421.42,2640 5355,2640 5355,2500 5320,2500
GND on Top Layer "TOP_LAYER_GND_P424" (solid, remove dead copper, pour order 424): 4970.02,1802.2 4977.22,1795 5275,1795 5275,1435 4970,1435
NetC4_1 on Top Layer "TOP_LAYER_NETC4_1_P414" (solid, remove dead copper, pour order 414): 4369.53,1400.62 4375,1395.15 4375,1330.98 4484.02,1330.98 4485,1330 4480,1335 4480,1415 4385.11,1415 4373.16,1403.05
VOUT_BOOST_1 on Top Layer "TOP_LAYER_VOUT_BOOST_1_P412" (solid, remove dead copper, pour order 412): 2584.79,591.99 2824.99,588.13 3099.79,309.71 3734.79,309.71 3830,309.71 3830,39.71 2959.79,39.71 2944.79,54.71 2904.79,94.71 2904.79,224.71 2904.79,239.71 2784.79,359.71 2783.76,358.68 2584.79,358.68
GND on Top Layer "TOP_LAYER_GND_P410" (solid, remove dead copper, pour order 410): 2944.79,1339.8 2944.79,1165.21 3077.5,1032.5 3085,815 3265,815 3265,580 4570,580 4570,310.1 3105.1,310.1 2830.2,585 2830.2,730 2830.2,1339.8
NetR133_1 on Top Layer "TOP_LAYER_NETR133_1_P342" (solid, remove dead copper, pour order 342): 2100,900 2530,900 2530,1600 2100,1600
NetD10_1 on Top Layer "TOP_LAYER_NETD10_1_P340" (solid, remove dead copper, pour order 340): 2110,2305 2110,1600 2210,1600 2530,1600 2530,2305
NetD10_2 on Top Layer "TOP_LAYER_NETD10_2_P332" (solid, remove dead copper, pour order 332): 1850,2316.2 2530,2316.2 2530,3100 1850,3100
NetD7_1 on Top Layer "TOP_LAYER_NETD7_1_P324" (solid, remove dead copper, pour order 324): 1285,2315 1850,2315 1850,3100 1285,3100
NetQ3_5 on Top Layer "TOP_LAYER_NETQ3_5_P318" (solid, remove dead copper, pour order 318): 2080,780 2080,560 2530,560 2530,900 2210,900 2210,780
NetC95_1 on Top Layer "TOP_LAYER_NETC95_1_P314" (solid, remove dead copper, pour order 314): 780,2220 979,2220 979,2150 1185,2150 1185,2850 990,2850 990,2655 786.36,2655
GND on Top Layer "TOP_LAYER_GND_P312" (solid, remove dead copper, pour order 312): 1920,620 2085,620 2085,780 1885,780 1885,620 1932.5,620.01
GND on Top Layer "TOP_LAYER_GND_P302" (solid, remove dead copper, pour order 302): 718.11,2615 869.04,2615 869.04,2448.5 806.61,2448.5 718.11,2448.5
NetD9_1 on Top Layer "TOP_LAYER_NETD9_1_P236" (solid, remove dead copper, pour order 236): 1179,2245 1249.79,2245 1254,2240.79 1254,1995 1179,2005 1179,2150
GND on Top Layer "TOP_LAYER_GND_P259" (solid, remove dead copper, pour order 259): 485,2020.5 589,2020.5 589,2220 779,2220 779,2394.99 774,2400 479,2400
NetD9_2 on Top Layer "TOP_LAYER_NETD9_2_P240" (solid, remove dead copper, pour order 240): 1789,1790 1894,1790 1894,1945 2095,1945 2095,2309 1187,2306 ccw(c1184,2306) 1184,2309 1184,1945 1184,1820 1384,1820 1384,1945 1789,1945
NetD11_2 on Top Layer "TOP_LAYER_NETD11_2_P243" (solid, remove dead copper, pour order 243): 1659,1045 1857.83,1045 1859,1043.83 1859,861 ccw(c1925,861) 1925,795 2040,795 ccw(c2030,860) 2095,870 2095,1860 ccw(c2035,1885) 2060,1945 1394,1945 1394,1815 1540,1520 1789,1520 1819,1520 cw(c1819,1480) 1859,1480 1859,1150.17 1659.17,1150.17
NetD14_2 on Top Layer "TOP_LAYER_NETD14_2_P248" (solid, remove dead copper, pour order 248): 1859,1441 1859,795 1178.81,795 1178.81,895.45 1178.81,1043.83 970.17,1043.83 964,1050 964,1150 1178.64,1150 1178.85,1323.14 1445,1360 1548.64,1520 1780,1520 cw(c1780,1441)
NetD15_2 on Top Layer "TOP_LAYER_NETD15_2_P251" (solid, remove dead copper, pour order 251): 641,1730.41 789.79,1730.41 789.79,1520.41 813.57,1520.41 871,1520.41 951,1520.41 1015,1522.63 1178.81,1310 1178.81,1189.81 1178.81,795 946,795 479,795 479,895.41 479,1520.41 636,1520.41 638.21,1522.63 638.21,1730.41
NetD16_2 on Top Layer "TOP_LAYER_NETD16_2_P255" (solid, remove dead copper, pour order 255): 479,1950 589,1950 589,1995 1174,1995 1185,1810 1050,1695 1014,1525 479,1525
BUCK_VOUT on Top Layer "TOP_LAYER_BUCK_VOUT_P306" (solid, remove dead copper, pour order 306): 3750,2400 4325,2400 4325,2150 4330,2145 4325,2150 3750,2150
GND on Top Layer "TOP_LAYER_GND_P308" (solid, remove dead copper, pour order 308): 4325,2400 4637.95,2400 4637.95,2302.95 4637.95,2137.95 4420,1920 4410.87,1500 4595,1500 4675,1500 4675,1420 4595,1420 4505,1420 4505,1050 4007.93,1050 4007.93,1250 4125,1250 4125,2150 4325,2150
NetC4_1 on Top Layer "TOP_LAYER_NETC4_1_P310" (solid, remove dead copper, pour order 310): 4032.1,1900 4135,1900 4135,1547.32 4050,1547.32 4050,1405 3983.9,1405 3980,1401.1 3980,1185 3910,1185 cw(c3910,1195) 3900,1195 3900,1807.07 3909.4,1826.79 cw(c4015.08,1776.39) 3936.74,1863.39 cw(c4032.1,1757.49)
NetD17_2 on Top Layer "TOP_LAYER_NETD17_2_P376" (solid, remove dead copper, pour order 376): 5470,2405 6305,2405 6305,2360.01 6410,2360.01 6410,2480 5545,2480 5545,2625 5514.5,2625 5425,2625 5425,2465.24 5426.18,2466.42 5470,2466.42
GND on Top Layer "TOP_LAYER_GND_P380" (solid, remove dead copper, pour order 380): 5389.99,3094.99 5594.99,3094.99 5634.99,3094.99 5634.99,2935 5520,2935 5520,2780.5 5634.99,2780.5 5635,2635 5405,2633.5 5405,2780.5 5435,2780.5 5435,2935 5391.5,2935
GND on Top Layer "TOP_LAYER_GND_P382" (solid, remove dead copper, pour order 382): 5735,2305 6020,2305 6020,2155 5735,2155
GND on Top Layer "TOP_LAYER_GND_P384" (solid, remove dead copper, pour order 384): 5190,1895 5190,2040.39 5315,2040.39 5315,1895
GND on Top Layer "TOP_LAYER_GND_P386" (solid, remove dead copper, pour order 386): 5800,1360 5962.99,1360 5920,1360 5920,1220 5800,1220
GND on Top Layer "TOP_LAYER_GND_P388" (solid, remove dead copper, pour order 388): 5565,1524.37 5290,1524.37 5290,1639.37 5565,1639.37
NetL5_1 on Top Layer "TOP_LAYER_NETL5_1_P390" (solid, remove dead copper, pour order 390): 5315,1025 5775,1024.98 5775,1120 5355,1120 5315,1060
GND on Top Layer "TOP_LAYER_GND_P392" (solid, remove dead copper, pour order 392): 5215,1025 5470,1025 5685,1025 5685,935 5383.78,935 5372.62,946.16 5363.78,955 5219.96,955 5215,955
5V-BUCK_OUT on Top Layer "TOP_LAYER_5V-BUCK_OUT_P394" (solid, remove dead copper, pour order 394): 5364.21,935 5763.54,935 5765,933.54 5763.54,855 5455,855 5455,805 5364.21,805
GND on Top Layer "TOP_LAYER_GND_P398" (solid, remove dead copper, pour order 398): 5265,2226.65 5456.65,2226.65 5460,2230 5460,2285 5570,2285 5570,2185 5266.65,2185 5265,2183.35
NetD6_1 on Top Layer "TOP_LAYER_NETD6_1_P400" (solid, remove dead copper, pour order 400): 2590,1485 2820,1485 2820,485 2590,485
GND on Top Layer "TOP_LAYER_GND_P402" (solid, remove dead copper, pour order 402): 2820.17,1690 2930,1690 2930,1180 2820.17,1180
FILTER_OUT on Top Layer "TOP_LAYER_FILTER_OUT_P406" (solid, remove dead copper, pour order 406): 3225,1000 3315,1000 3315,1135 3225,1135
GND on Top Layer "TOP_LAYER_GND_P418" (solid, remove dead copper, pour order 418): 5604.57,1979.97 5604.57,2115 5729.57,2115 5729.57,1979.97
GND on Top Layer "TOP_LAYER_GND_P420" (solid, remove dead copper, pour order 420): 5729.69,1836 5892.68,1836 5894.69,1834 5894.69,1696 5729.69,1696
GND on Top Layer "TOP_LAYER_GND_P422" (solid, remove dead copper, pour order 422): 5305,1304.37 5030,1304.37 5030,1419.37 5305,1419.37
BOOST_VOUT/BUCK_VIN on Top Layer "TOP_LAYER_BOOST_VOUT/BUCK_VIN_P448" (solid, remove dead copper, pour order 448): 4308.82,1800 4460,1800 4475.59,1800 4494.56,1781.03 4494.37,1780.84 4494.37,1640.43 4314.57,1640.43 4310,1645
GND on Top Layer "TOP_LAYER_GND_P454" (solid, remove dead copper, pour order 454): 4065,1401.02 4154.92,1401.02 4155,1401.1 4150,1396.1 4150,1345 4064,1345 4059,1340 4057.73,1341.27 4057.73,1399.98
GND on Top Layer "TOP_LAYER_GND_P462" (solid, remove dead copper, pour order 462): 3330,835 3415,835 3415,760.47 3410.47,765 3330,765
GND on Top Layer "TOP_LAYER_GND_P464" (solid, remove dead copper, pour order 464): 3050,2600 3130,2600 3130,2508.19 3129.69,2508.5 3051.5,2508.5
GND on Top Layer "TOP_LAYER_GND_P466" (solid, remove dead copper, pour order 466): 2860,2385 2975,2385 2975,2245 2973.5,2246.5 2860,2246.5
